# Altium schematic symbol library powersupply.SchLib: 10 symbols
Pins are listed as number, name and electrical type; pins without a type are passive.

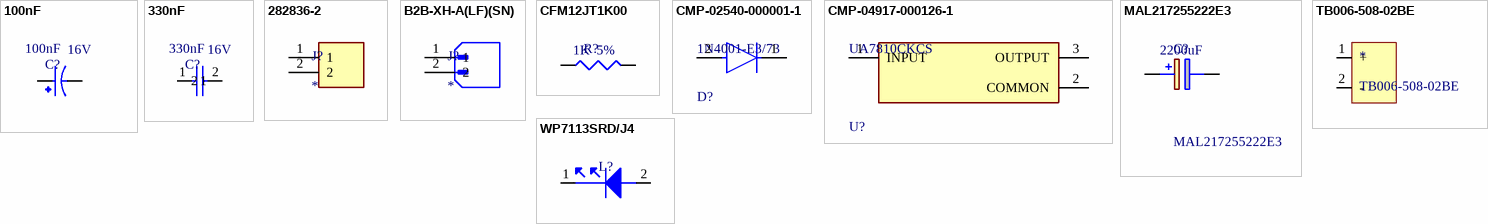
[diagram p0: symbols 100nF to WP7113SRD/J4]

## 100nF
designator C?  Voltage: 16V  (hidden comment: 100nF)
Aluminum Electrolytic Capacitor, Polarized, Aluminum (wet), 50V, 20% +Tol, 20% -Tol, 100nF, Through Hole Mount; Manufacturer: Panasonic; Manufacturer Part Number: EEA-GA1C100; Manufacturer Series: GA; Dielectric Material: Aluminium; Leakage Current: 3uA; Ripple Current: 30mA; Tan Delta: 0.18
footprint 100nF_Capacitor - duplicate
pins: 1, 2

## 330nF
designator C?  Voltage: 16V  (hidden comment: 330nF)
Ceramic Capacitor, Ceramic, 16V, 10% +Tol, 10% -Tol, SL0, 120ppm/Cel TC, 330nF, Through Hole Mount; Manufacturer: Vishay BCcomponents; Manufacturer Part Number: S220K25SL0N63L6R
footprint 330nF_Capacitor - duplicate1
pins: 1, 2

## 282836-2
designator J?
Terminal Block Connector Wire Receptacle 2 5 mm 30-16 AWG Green 13.5 A 300 V ¦ TE Connectivity 282836-2
footprint TE_282836-2
pins: 1, 2

## B2B-XH-A(LF)(SN)
designator J?
Connector Header Through Hole 2 position 0.098 (2.50mm); MF: JST Sales America Inc.; MP: B2B-XH-A(LF)(SN)
footprint JST_B2B-XH-A(LF)(SN)
pins: 1, 2

## CFM12JT1K00
designator R?  Resistance: 1K  Tolerance: 5%  (hidden comment: CFM12JT1K00)
Fixed Resistor, Carbon Film, 0.5W, 1000ohm, 350V, 5% +/-Tol, -400,0ppm/Cel, Through Hole Mount; Manufacturer: Stackpole Electronics; Power: 500mW; Rated Temperature: 70°C; Value: 1kR; Temperature Coefficient: 400ppm/°C; Lead Diameter: 0.55mm; Lead Length: 28mm; Package Diameter: 2.3mm; Package Length: 6mm
footprint Resister
pins: 1, 2

## CMP-02540-000001-1
designator D?, comment 1N4001-E3/73
DIODE GEN PURP 50V 1A DO204AL; Manufacturer: Vishay; Max Surge Forward Current: 30A; Value: 15pF; Peak Reverse Current: 5uA; Max Junction Temp: +150°C
footprint FP-1N4001-E3-73-MFG
pins: 1 C, 2 A

## CMP-04917-000126-1
designator U?, comment UA7810CKCS
IC REG LINEAR 10V 1.5A TO220-3; Output Type: Fixed; Number of Regulators: 1; Dropout Voltage: 2V; Min Output Voltage: 9.5V; Power Supply Rejection Ratio (PSRR): 71dB; Min Input Voltage: 12.5V; Quiescent Current: 8mA; Polarity: Positive; Max Output Voltage: 10.5V; Max Input Voltage: 28V
footprint FP-KCS0003B-MFG
pins: 1 INPUT (power), 2 COMMON (power), 3 OUTPUT (power)

## MAL217255222E3
designator C?  value 2200uF
Aluminum Electrolytic Capacitors Radial Miniature, Low Impedance, Automotive Grade; Manufacturer_Name: Vishay; Geometry.Height: 22mm
footprint CAPPRD500W60D1275H2200
pins: 1 +, 2 -

## TB006-508-02BE
designator *
Barrier Strip Terminal Block; Manufacturer: CUI Devices
footprint terminalbox
pins: 1 +, 2 -

## WP7113SRD/J4
designator L?  (value not drawn)
LED Uni-Color SB. Red 660nm 2-Pin T-1 3/4 Bulk; Manufacturer: Kingbright
footprint LEDRD254W57D500H1070
pins: 1, 2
